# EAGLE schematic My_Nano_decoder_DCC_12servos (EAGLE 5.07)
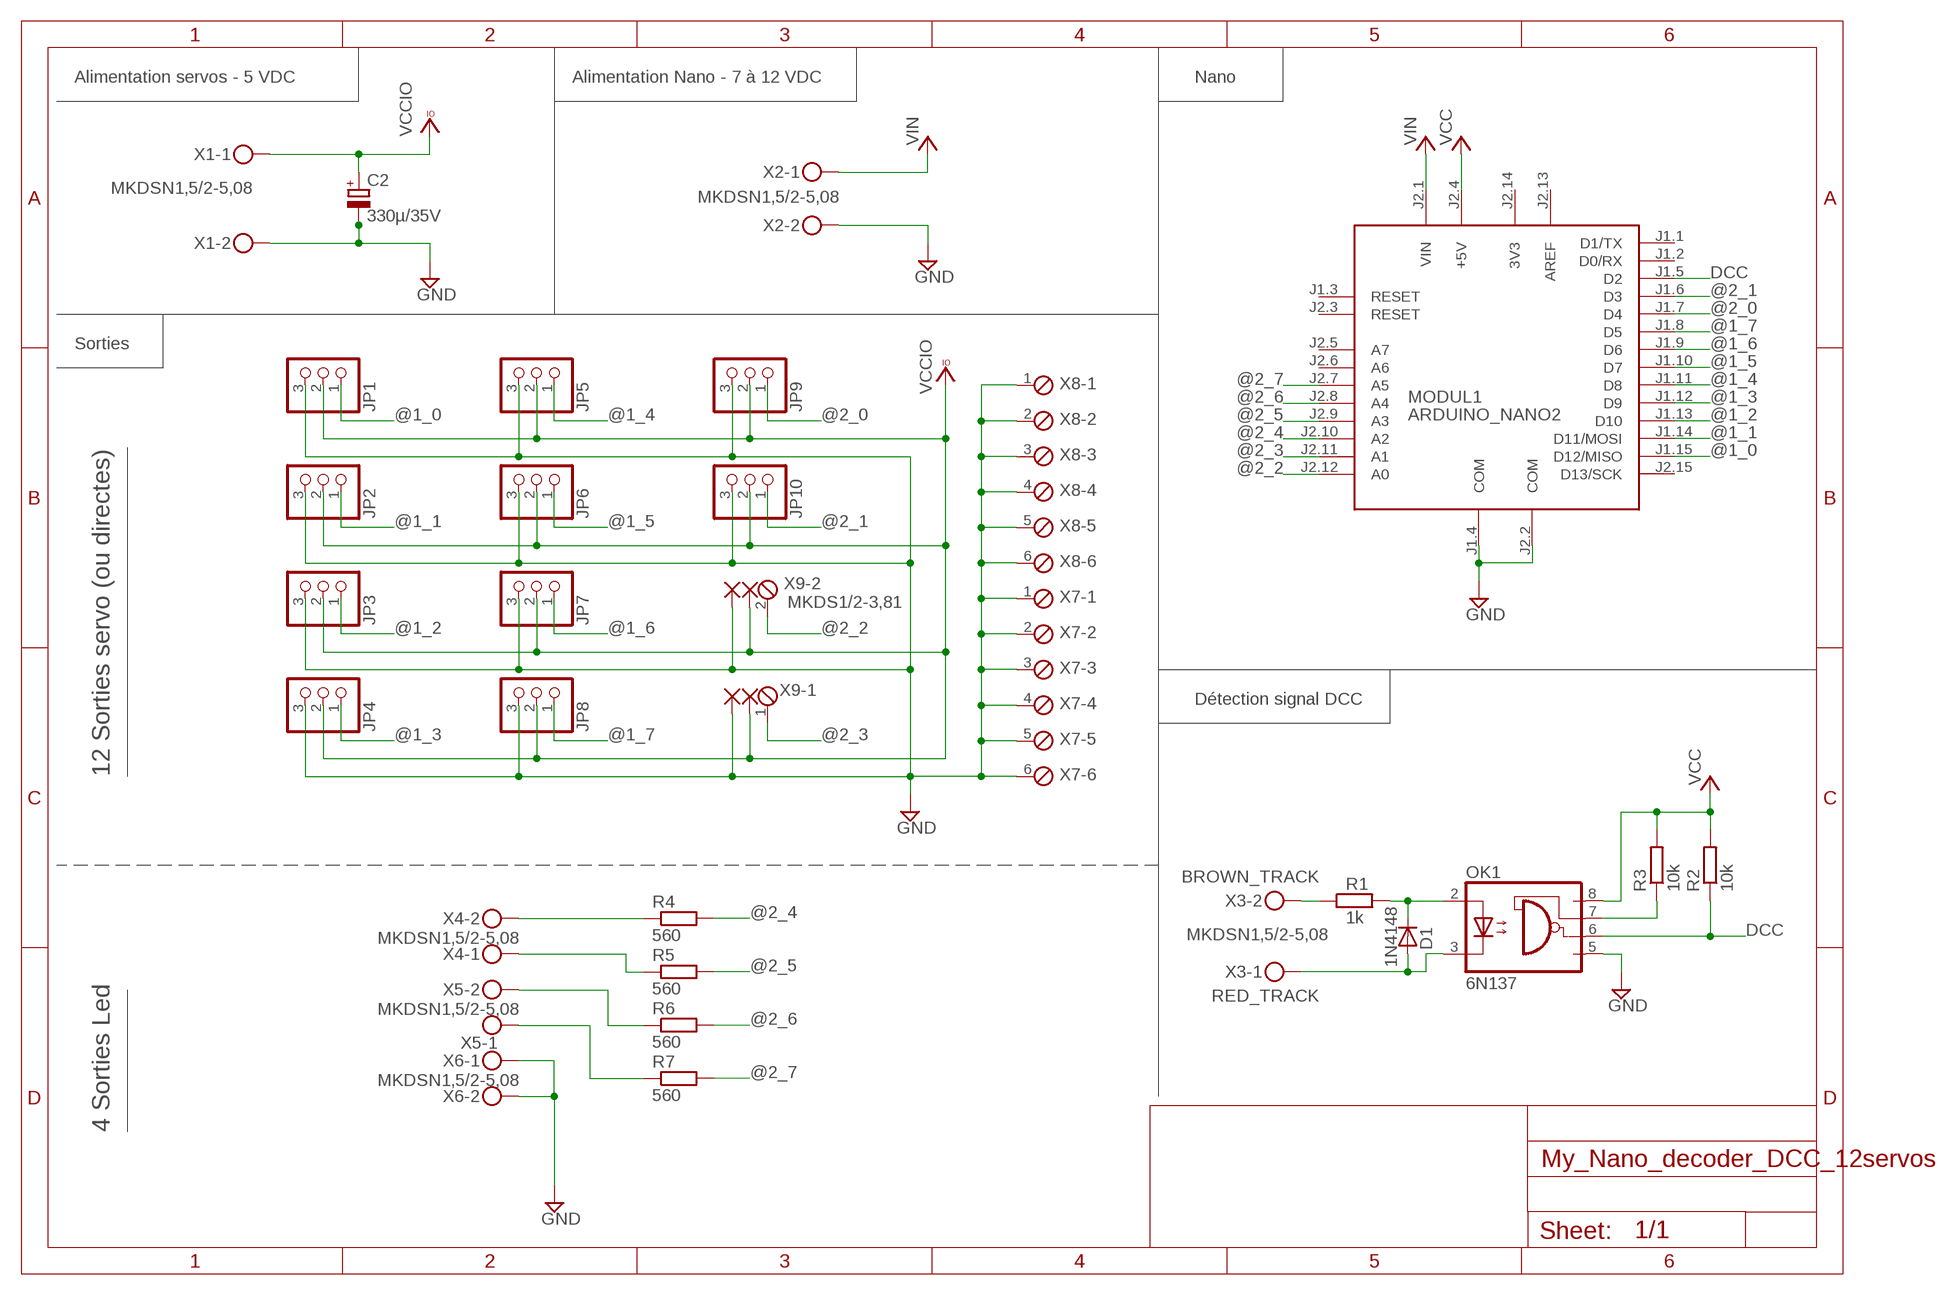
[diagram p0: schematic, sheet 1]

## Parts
C2  330µ/35V  C-POL  [E2.5/5-6]
D1  1N4148  1N4148DO35-7  [DO35-7]
JP1  PINHD-1X3  [1X03]
JP2  PINHD-1X3  [1X03]
JP3  PINHD-1X3  [1X03]
JP4  PINHD-1X3  [1X03]
JP5  PINHD-1X3  [1X03]
JP6  PINHD-1X3  [1X03]
JP7  PINHD-1X3  [1X03]
JP8  PINHD-1X3  [1X03]
JP9  PINHD-1X3  [1X03]
JP10  PINHD-1X3  [1X03]
MODUL1  ARDUINO_NANO2  [ARDUINO_NANO2]
OK1  6N137  [DIL08]
R1  1k  R-EU_0207/10  [0207/10]
R2  10k  R-EU_0207/10  [0207/10]
R3  10k  R-EU_0207/10  [0207/10]
R4  560  R-EU_0207/10  [0207/10]
R5  560  R-EU_0207/10  [0207/10]
R6  560  R-EU_0207/10  [0207/10]
R7  560  R-EU_0207/10  [0207/10]
U$1  PAD  [PAD]
U$2  PAD  [PAD]
U$3  PAD  [PAD]
U$4  PAD  [PAD]
X1  MKDSN1,5/2-5,08  [MKDSN1,5/2-5,08]
X2  MKDSN1,5/2-5,08  [MKDSN1,5/2-5,08]
X3  MKDSN1,5/2-5,08  [MKDSN1,5/2-5,08]
X4  MKDSN1,5/2-5,08  [MKDSN1,5/2-5,08]
X5  MKDSN1,5/2-5,08  [MKDSN1,5/2-5,08]
X6  MKDSN1,5/2-5,08  [MKDSN1,5/2-5,08]
X7  MPT6  [6POL254]
X8  MPT6  [6POL254]
X9  MKDS1/2-3,81  [2POL381]

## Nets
@1_0: JP1.1 MODUL1.J1.15(D12/MISO)
@1_1: JP2.1 MODUL1.J1.14(D11/MOSI)
@1_2: JP3.1 MODUL1.J1.13(D10)
@1_3: JP4.1 MODUL1.J1.12(D9)
@1_4: JP5.1 MODUL1.J1.11(D8)
@1_5: JP6.1 MODUL1.J1.10(D7)
@1_6: JP7.1 MODUL1.J1.9(D6)
@1_7: JP8.1 MODUL1.J1.8(D5)
@2_0: JP9.1 MODUL1.J1.7(D4)
@2_1: JP10.1 MODUL1.J1.6(D3)
@2_2: MODUL1.J2.12(A0) X9.2
@2_3: MODUL1.J2.11(A1) X9.1
@2_4: MODUL1.J2.10(A2) R4.2
@2_5: MODUL1.J2.9(A3) R5.2
@2_6: MODUL1.J2.8(A4) R6.2
@2_7: MODUL1.J2.7(A5) R7.2
BROWN_TRACK: R1.1 X3.2
DCC: MODUL1.J1.5(D2) OK1.6(VO) R2.1
GND: C2.- C2.-1 JP1.3 JP2.3 JP3.3 JP4.3 JP5.3 JP6.3 JP7.3 JP8.3 JP9.3 JP10.3 MODUL1.J1.4(COM) MODUL1.J2.2(COM) OK1.5(GND) U$1. U$3. X1.2 X2.2 X6.1 X6.2 X7.1 X7.2 X7.3 X7.4 X7.5 X7.6 X8.1 X8.2 X8.3 X8.4 X8.5 X8.6
N$2: D1.C OK1.2(A) R1.2
N$4: OK1.7(VE) R3.1
N$7: R4.1 X4.2
N$8: R5.1 X4.1
N$9: R6.1 X5.2
N$10: R7.1 X5.1
RED_TRACK: D1.A OK1.3(C) X3.1
VCC: MODUL1.J2.4(+5V) OK1.8(VCC) R2.2 R3.2
VCCIO: C2.+ JP1.2 JP2.2 JP3.2 JP4.2 JP5.2 JP6.2 JP7.2 JP8.2 JP9.2 JP10.2 U$2. U$4. X1.1
VIN: MODUL1.J2.1(VIN) X2.1
Unconnected: MODUL1.J1.1(D1/TX) MODUL1.J1.2(D0/RX) MODUL1.J1.3(RESET) MODUL1.J2.3(RESET) MODUL1.J2.5(A7) MODUL1.J2.6(A6) MODUL1.J2.15(D13/SCK)

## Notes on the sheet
- Alimentation servos - 5 VDC | Alimentation Nano - 7 à 12 VDC | Nano
- Sorties
- Détection signal DCC
- 12 Sorties servo (ou directes)
- 4 Sorties Led

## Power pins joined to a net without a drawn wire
3V3: MODUL1.J2.14(3V3)
AREF: MODUL1.J2.13(AREF)

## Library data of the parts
C2 = rcl_perso:C-POL
D1 = diode:1N4148: DIODE
JP1-JP10 = my-pinhead:PINHD-1X3: PIN HEADER
MODUL1 = arduino_Nano:ARDUINO_NANO2: Arduino Nano2 Auto generated by modulcreator.ulp \;; ANZAHL: 2; MODUL: TRUE; STECKX0: -76200; STECKX1: 76200; STECKY0: 177800; STECKY1: 177800
OK1 = optocoupler:6N137: MOTOROLA OPTO COUPLER
R1-R7 = rcl:R-EU_: RESISTOR, European symbol
U$1-U$4 = my-pinhead:PAD
X1-X6 = con-phoenix-508:MKDSN1,5/2-5,08: MKDSN 1,5/ 2-5,08 Printklemme
X7 X8 = con-phoenix-254:MPT6: PHOENIX CONNECTOR
X9 = my-conn-phoenix-381:MKDS1/2-3,81: MKDS 1/2-3,81 - Order No. 1727010 (RS-Online - 101-5384)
